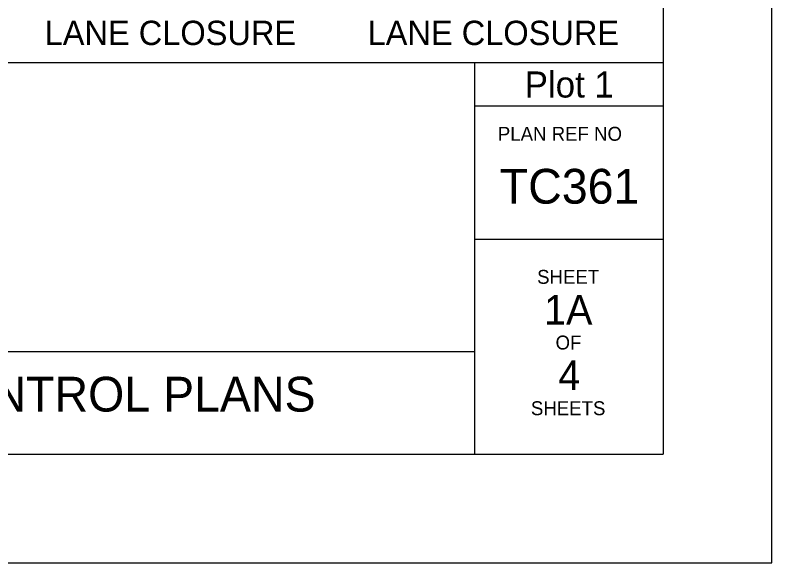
# Model space of a CAD drawing. Extents: x 99958 to 100176, y 99935 to 100011.
# Drawn here: x 100013.887 to 100016.062, y 99999.687 to 100001.262 of the extents above; entities that cross this region are included whole.
import ezdxf

# ---------------------------------------------------------------- set-up
doc = ezdxf.new("R2010")
doc.units = 0
for name, color, linetype in [('SH_GI_PlotLimits', 7, 'Continuous'), ('SH_GI_SheetBorder', 7, 'Continuous'), ('SH_GI_SheetLocationText', 7, 'Continuous'), ('SH_GI_SheetTextInCells', 7, 'Continuous'), ('SH_GI_TitleBlockText', 7, 'Continuous'), ('TR_SN_ConstructionSigns', 7, 'Continuous')]:
    doc.layers.add(name, color=color, linetype=linetype)

msp = doc.modelspace()

# ---------------------------------------------------------------- linework, layer by layer
at = {"layer": 'SH_GI_PlotLimits'}
msp.add_lwpolyline([(99999.0625, 99999.6875), (100016.0625, 99999.6875), (100016.0625, 100010.6875), (99999.0625, 100010.6875)], close=True, dxfattribs=at)
at = {"layer": 'SH_GI_SheetBorder'}
for p, q in [((100015.75, 100010.375), (100015.75, 100000)), ((100000, 100001.1259), (100015.75, 100001.1259)), ((100015.2079, 100001.1259), (100015.2079, 100000)), ((100015.2079, 100001.0008), (100015.75, 100001.0008)), ((100015.2079, 100000.6176), (100015.75, 100000.6176)), ((100012.2055, 100000.2955), (100015.2079, 100000.2955)), ((100000, 100000), (100015.75, 100000))]:
    msp.add_line(p, q, dxfattribs=at)

# ---------------------------------------------------------------- texts
msp.add_text('PLAN REF NO', height=0.040032, dxfattribs=at).set_placement((100015.2747, 100000.9008))
at = {"layer": 'SH_GI_SheetLocationText'}
msp.add_text('Plot 1', height=0.075, dxfattribs=at).set_placement((100015.3518, 100001.025))
at = {"layer": 'SH_GI_SheetTextInCells'}
for s, p in [('SHEET', (100015.3877, 100000.4896)), ('OF', (100015.4406, 100000.3008)), ('SHEETS', (100015.3698, 100000.112))]:
    msp.add_text(s, height=0.04003, dxfattribs=at).set_placement(p)
at = {"layer": 'SH_GI_TitleBlockText'}
for s, height, p in [('TC361', 0.1, (100015.2803, 100000.72)), ('1A', 0.085, (100015.4076, 100000.3723)), ('4', 0.085, (100015.4485, 100000.1843)), ('TYPICAL TRAFFIC CONTROL PLANS', 0.1, (100012.4251, 100000.1224))]:
    msp.add_text(s, height=height, dxfattribs=at).set_placement(p)
at = {"layer": 'TR_SN_ConstructionSigns'}
for p in [(100013.9718, 100001.1759), (100014.9003, 100001.1759)]:
    msp.add_text('LANE CLOSURE', height=0.07, rotation=360, dxfattribs=at).set_placement(p)

doc.saveas('drawing.dxf')
